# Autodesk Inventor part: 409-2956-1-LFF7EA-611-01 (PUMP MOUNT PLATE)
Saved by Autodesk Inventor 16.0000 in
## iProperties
Created: 2010-06
Part Number: 409-2956-1-LFF7EA-611-01 (PUMP MOUNT PLATE)
Cost Center: 0 lbmass
Material: A36 STEEL PLATE
Document SubType Name: Sheet Metal
Designer: S. Boerckel
Authority: 0 in^3
Mass: 72473.8 g
Surface Area: 10335.7 cm^2
Volume: 9220.59 cm^3
Density: 7.86 g/cm^3
Sheet Metal Rule: 3/4"Thk
Description: PUMP MOUNT PLATE
Flat Pattern Width: 40.64 cm
Flat Pattern Length: 119.38 cm
Flat Pattern Area: 4851.6 cm^2
Sheet Metal Width: 47.0000 in
Sheet Metal Length: 752.0000 in^2
User Status: BURN/DRILL
SaveDate: 2008-01-15
SaveTime: 10:24
FileName: Sheet Metal
Wide: =<Flat Pattern Width>cm
Length: =<Flat Pattern Length>cm
Thickness: 0.7500 in
SMR: =<Sheet Metal Rule> - <Material>
Author: S. Boerckel
Revision Number: 0
Subject: DEMIN WATER FORWARDING PUMP SKID-7EA
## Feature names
1. Hole1
2. Plate1
